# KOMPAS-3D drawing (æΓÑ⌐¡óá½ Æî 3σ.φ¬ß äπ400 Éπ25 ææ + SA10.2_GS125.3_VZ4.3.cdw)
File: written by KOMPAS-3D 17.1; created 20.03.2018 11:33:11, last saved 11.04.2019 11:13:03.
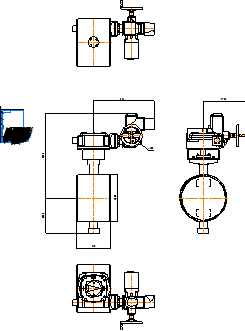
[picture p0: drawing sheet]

Sheet 1: A4, portrait

Title block, sheet 1: name: Стейнвал ТМ 3х.экс / Ду400 Ру25 СС + SA10.2_GS125.3_VZ4.3; material: Внимание! Данный продукт является объектом авторского права ООО «Торговый Дом АДЛ». / Запрещается изменение, копирование, распространение / (в том числе путем копирования на другие сайты и ресурсы в Интернете) / или любое иное использование информации и объектов без предварительного / согласия правообладателя (ООО «Торговый Дом АДЛ»).; mass: 97,3; sheets: 1; organisation: ООО "Торговый дом АДЛ"; sheet format: A4; stored path: \\adlc.lan\data\АДЛ_ПКД\3D-модели\ADL production\Дисковые поворотные затворы СТЕЙНВАЛ\Трехэксцентриковый\Стейнвал c-c\С эл.приводом\KOMPAS 2D\Стейнвал ТМ 3х.экс Ду400 Ру25 СС + SA10.2_GS125.3_VZ4.3.cdw

Views: Проекционный вид 3, Проекционный вид 4
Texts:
  kka
  adl
Dimensions and other numbers on the sheet: 1:1; 1; 97,3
